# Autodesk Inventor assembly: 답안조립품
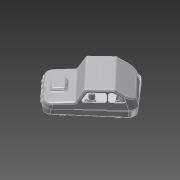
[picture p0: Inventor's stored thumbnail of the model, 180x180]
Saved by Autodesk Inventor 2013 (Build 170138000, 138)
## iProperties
Created: 2015-05
Part Number: 답안조립품
Document SubType Name: Assembly
Designer: WINDOWS7
Author: WINDOWS7
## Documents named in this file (6)
- C:\Users\WINDOWS7\Desktop\450508V1006\답안조립품.iam
- C:\Users\WINDOWS7\Desktop\450508V1006\본체.ipt
- C:\Users\WINDOWS7\Desktop\450508V1006\커버.ipt
- C:\Users\WINDOWS7\Desktop\450508V1006\바퀴고정부.ipt
- C:\Users\WINDOWS7\Desktop\450508V1006\바퀴.ipt
- C:\Users\WINDOWS7\Desktop\450508V1006\M4x10.ipt
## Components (4 placed, 1 different names)
1. M4x10:1
2. M4x10:2
3. M4x10:3
4. M4x10:4
